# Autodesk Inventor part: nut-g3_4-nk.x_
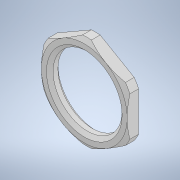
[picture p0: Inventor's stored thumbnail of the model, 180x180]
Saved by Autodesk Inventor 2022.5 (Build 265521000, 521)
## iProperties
Created: 2022-07
Part Number: nut-g3_4-nk.x_
Material: 一般
Document SubType Name: Modeling
Designer: ImaoCorp
Density: 1 g/cm^3
Appearance: 既定
Sending System: SOLIDWORKS 2020-2020296
MC: AMD64
MC_MODEL: Intel64 Family 6 Model 60 Stepping 3, GenuineIntel
OS: Windows_NT
FRU: Parasolid Version 31.1, build 290,  3- 9-2020
FORMAT: text
GUISE: transmit
KEY: nut-g3_4-nk
FILE: nut-g3_4-nk.x_t
DATE: Fri Jul 15 15:54:29 2022
Author: ImaoCorp
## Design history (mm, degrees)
feature "Brass nut GH. 3_4-NK"
node "ソリッド1"
